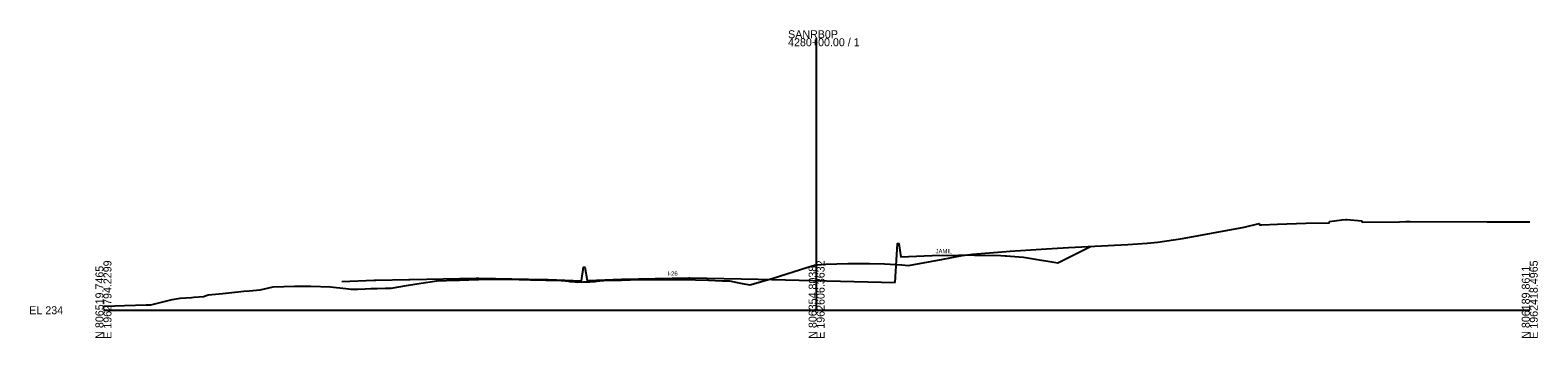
# Model space of a CAD drawing. Extents: x 1995641 to 1997170, y 790368 to 809963.
# Drawn here: x 1995641 to 1996170, y 790868 to 790976 of the extents above; entities that cross this region are included whole.
import ezdxf

# ---------------------------------------------------------------- set-up
doc = ezdxf.new("R2010")
doc.units = 0
for name, color, linetype in [('Default', 7, 'Continuous'), ('RD_GPK_XS_Cell', 7, 'Continuous'), ('RD_Sketch1', 7, 'Continuous'), ('RD_XS_ExGround', 7, 'Continuous'), ('RD_XS_Pave', 7, 'Continuous')]:
    doc.layers.add(name, color=color, linetype=linetype)

msp = doc.modelspace()

# ---------------------------------------------------------------- linework, layer by layer
at = {"layer": 'RD_GPK_XS_Cell'}
for p, q in [((1995917.06, 790878.11), (1995917.06, 790973.56)), ((1995667.06, 790878.11), (1995917.06, 790878.11)), ((1995917.06, 790878.11), (1996167.06, 790878.11))]:
    msp.add_line(p, q, dxfattribs=at)
at = {"layer": 'RD_XS_ExGround'}
msp.add_lwpolyline([(1995667.06, 790879.58), (1995667.64, 790879.6), (1995674.46, 790879.79), (1995682.03, 790879.98), (1995683.7, 790880.02), (1995691.09, 790881.86), (1995694.01, 790882.35), (1995697.98, 790882.62), (1995698.8, 790882.71), (1995702.08, 790882.92), (1995703.73, 790883.47), (1995707.6, 790883.86), (1995709.98, 790884.16), (1995716.25, 790884.81), (1995718.19, 790884.92), (1995722.02, 790885.33), (1995726.59, 790886.38), (1995734, 790886.54), (1995736.31, 790886.6), (1995739.78, 790886.53), (1995746.71, 790886.29), (1995752.03, 790885.7), (1995753.91, 790885.5), (1995756.2, 790885.46), (1995758.86, 790885.58), (1995760.75, 790885.79), (1995762.96, 790885.74), (1995765.89, 790885.84), (1995767.91, 790885.91), (1995773.94, 790886.88), (1995778.45, 790887.57), (1995783.95, 790888.42), (1995787.28, 790888.53), (1995791.91, 790888.69), (1995801.8, 790888.99), (1995804.16, 790889.06), (1995812.78, 790888.92), (1995815.77, 790888.87), (1995816.79, 790888.84), (1995827.49, 790888.53), (1995829.03, 790888.42), (1995830.03, 790888.35), (1995830.5, 790888.17), (1995832.37, 790888.07), (1995833.24, 790888.01), (1995835.32, 790888.04), (1995836.23, 790888.05), (1995837.52, 790888.11), (1995839.22, 790888.18), (1995839.46, 790888.24), (1995839.92, 790888.28), (1995840.18, 790888.41), (1995841.04, 790888.46), (1995842.43, 790888.53), (1995848.65, 790888.71), (1995854.77, 790888.88), (1995861.94, 790888.91), (1995866.88, 790888.94), (1995874.61, 790888.75), (1995879.19, 790888.63), (1995883.99, 790888.49), (1995886.55, 790888.41), (1995889.81, 790887.77), (1995890.99, 790887.55), (1995893.67, 790887.08), (1995901.48, 790889.26), (1995914.04, 790893.18), (1995916.27, 790893.95), (1995917.34, 790894.07), (1995920.31, 790894.29), (1995927.98, 790894.5), (1995930.76, 790894.54), (1995933.07, 790894.54), (1995935.6, 790894.48), (1995940.91, 790894.36), (1995946.89, 790894), (1995949.33, 790893.8), (1995958.84, 790895.56), (1995960.85, 790895.89), (1995968.11, 790897.27), (1995971.78, 790897.75), (1995984.97, 790898.84), (1995995.83, 790899.59), (1996005.37, 790900.17), (1996026.2, 790901.24), (1996032.95, 790901.62), (1996036.68, 790901.99), (1996045.3, 790903.32), (1996066.92, 790907.29), (1996072.22, 790908.53), (1996072.33, 790908.03), (1996073.1, 790908.06), (1996078.6, 790908.27), (1996088.59, 790908.62), (1996096.76, 790908.78), (1996096.86, 790909.28), (1996101.14, 790909.82), (1996102.54, 790909.91), (1996102.96, 790909.93), (1996108.17, 790909.46), (1996108.27, 790908.97), (1996121.38, 790909.19), (1996123.65, 790909.25), (1996125.13, 790909.24), (1996152.17, 790909.14), (1996165.06, 790909.1), (1996165.98, 790909.1), (1996167.06, 790909.09)], dxfattribs=at)
at = {"layer": 'RD_XS_Pave'}
for points in [[(1995944.61, 790887.83), (1995945.37, 790901.51), (1995945.87, 790901.51), (1995946.62, 790896.84), (1995949.32, 790896.95), (1995957.6, 790897.28), (1995966.86, 790897.47), (1995969.6, 790897.53), (1995972.36, 790897.47), (1995981.6, 790897.29), (1995983.14, 790897.26), (1995983.6, 790897.25), (1995984.99, 790897.14), (1995989.6, 790896.77), (1995992.38, 790896.31), (1996001.6, 790894.77), (1996003.95, 790895.95), (1996013.06, 790900.51)], [(1995750.6, 790888.18), (1995762.01, 790888.63), (1995762.6, 790888.66), (1995774.06, 790888.94), (1995774.6, 790888.95), (1995797.68, 790889.41), (1995798.6, 790889.43), (1995821.86, 790888.95), (1995822.6, 790888.94), (1995822.97, 790888.92), (1995834.61, 790888.46), (1995835.36, 790893.25), (1995835.86, 790893.25), (1995836.61, 790888.58), (1995836.93, 790888.6), (1995848.61, 790889.06), (1995872.22, 790889.52), (1995872.61, 790889.53), (1995896.61, 790889.05), (1995944.61, 790887.83)]]:
    msp.add_lwpolyline(points, dxfattribs=at)

# ---------------------------------------------------------------- texts
at = {"layer": 'Default'}
msp.add_text('-', height=0.0001, dxfattribs=at).set_placement((1995667.06, 790878.11))
msp.add_text('-', height=0.0001, dxfattribs=at).set_placement((1995667.06, 790878.11))
at = {"layer": 'RD_GPK_XS_Cell'}
for s, p in [('SANRB0P', (1995907.06, 790973.56)), ('4280+00.00 / 1', (1995907.06, 790970.76)), ('EL 234', (1995641.06, 790876.71))]:
    msp.add_text(s, height=2.8, dxfattribs=at).set_placement(p)
for s, p in [('N 806519.7465', (1995667.06, 790868.11)), ('E 1962794.2299', (1995669.86, 790868.11)), ('N 806354.8038', (1995917.06, 790868.11)), ('E 1962606.3632', (1995919.86, 790868.11)), ('N 806189.8611', (1996167.06, 790868.11)), ('E 1962418.4965', (1996169.86, 790868.11))]:
    msp.add_text(s, height=2.8, rotation=90, dxfattribs=at).set_placement(p)
at = {"layer": 'RD_Sketch1'}
msp.add_text('249.93', height=0.1, dxfattribs=at).set_placement((1995916.85, 790893.94))
at = {"layer": 'RD_XS_Pave'}
for s, p in [('JAMIL', (1995958.77, 790898.09)), ('I-26', (1995864.78, 790890.24))]:
    msp.add_text(s, height=1.5, dxfattribs=at).set_placement(p)

doc.saveas('drawing.dxf')
